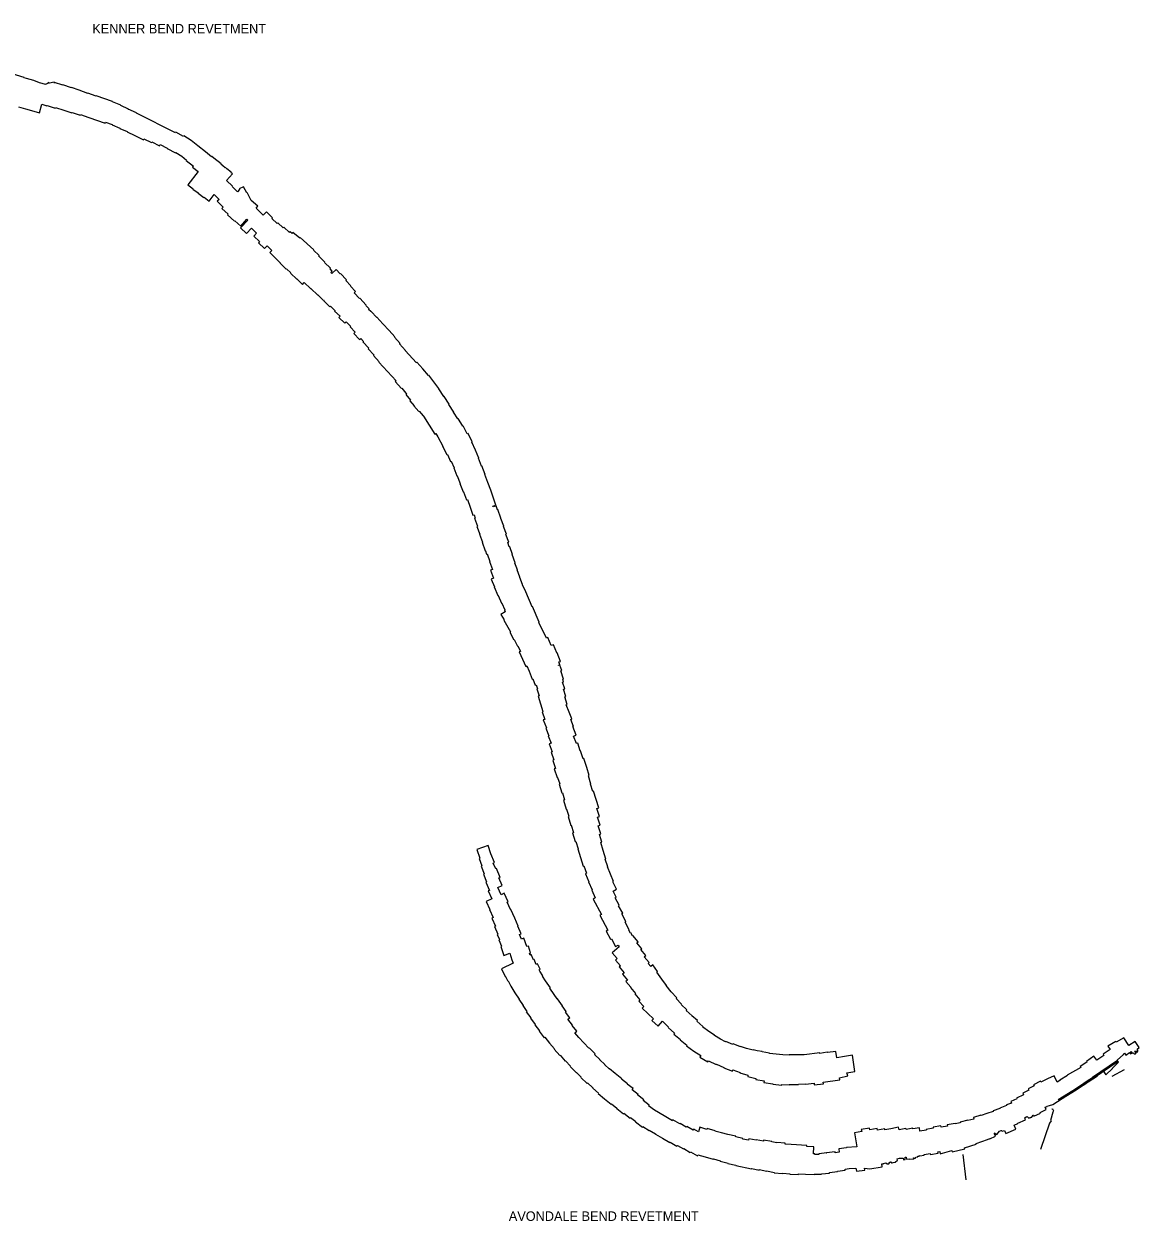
# Model space of a CAD drawing. Extents: x 2650582 to 3923188, y 277893 to 989177.
# Drawn here: x 3624994 to 3643767, y 517433 to 537580 of the extents above; entities that cross this region are included whole.
import ezdxf

# ---------------------------------------------------------------- set-up
doc = ezdxf.new("R2010")
doc.units = 0
doc.layers.add('Level 3', color=7, linetype='Continuous')

msp = doc.modelspace()

# ---------------------------------------------------------------- linework, layer by layer
at = {"layer": 'Level 3'}
for p, q in [((3643403, 520136), (3642982, 519851)), ((3643409, 520127), (3642988, 519842)), ((3643414, 520119), (3642994, 519834)), ((3643517, 519977), (3643307, 519865)), ((3640799, 518556), (3640852, 518129))]:
    msp.add_line(p, q, dxfattribs=at)
for points in [[(3625365, 536560), (3625256, 536591), (3625256, 536591), (3625158, 536626), (3625158, 536628), (3625039, 536663), (3625038, 536659), (3624998, 536673), (3624999, 536678), (3624794, 536742), (3624791, 536736), (3624564, 536810), (3624567, 536823), (3624445, 536849), (3624445, 536853), (3624408, 536861), (3624322, 536889), (3624323, 536894), (3624282, 536903)], [(3628478, 535078), (3628483, 535086), (3628409, 535141), (3628385, 535164), (3628382, 535161), (3628343, 535191), (3628310, 535218), (3628315, 535226), (3628189, 535319), (3628155, 535348), (3628154, 535346), (3628048, 535426), (3628052, 535430), (3627924, 535531), (3627809, 535621), (3627809, 535620), (3627685, 535699), (3627678, 535688), (3627550, 535756), (3627544, 535746), (3627289, 535876), (3627290, 535878), (3627160, 535944), (3627161, 535946), (3627014, 536016), (3627013, 536015), (3626888, 536077), (3626891, 536083), (3626751, 536143), (3626753, 536148), (3626624, 536205), (3626627, 536215), (3626484, 536270), (3626486, 536274), (3626211, 536369), (3626210, 536367), (3626070, 536415), (3626070, 536412), (3625923, 536464), (3625923, 536463), (3625796, 536508), (3625795, 536505), (3625650, 536556), (3625647, 536548), (3625511, 536596), (3625506, 536582), (3625501, 536602), (3625427, 536584), (3625401, 536592), (3625396, 536576), (3625364, 536568), (3625365, 536560)], [(3624902, 536186), (3625021, 536152), (3625022, 536153), (3625122, 536124), (3625121, 536123), (3625256, 536084), (3625298, 536229)], [(3625298, 536229), (3625380, 536199), (3625384, 536210), (3625521, 536161), (3625526, 536174), (3625663, 536127), (3625664, 536130), (3625802, 536082), (3625805, 536091), (3625942, 536042), (3625946, 536054), (3626084, 536006), (3626085, 536008), (3626360, 535912), (3626366, 535929), (3626482, 535885), (3626481, 535883), (3626610, 535826), (3626608, 535823), (3626732, 535769), (3626731, 535767), (3626861, 535703), (3626860, 535700), (3627005, 535630), (3627013, 535647), (3627139, 535583), (3627147, 535598), (3627279, 535531), (3627288, 535549), (3627407, 535487), (3627405, 535482), (3627545, 535408), (3627549, 535416), (3627650, 535352), (3627731, 535290), (3627726, 535284), (3627848, 535187), (3627834, 535170), (3627928, 535099)], [(3627928, 535099), (3627755, 534870), (3627842, 534804), (3627840, 534801), (3627927, 534735), (3627926, 534734), (3628025, 534659), (3628029, 534664), (3628115, 534599), (3628197, 534707)], [(3628902, 534481), (3628930, 534514), (3628818, 534610), (3628753, 534742), (3628745, 534738), (3628692, 534841), (3628619, 534803), (3628623, 534795), (3628589, 534757), (3628500, 534842), (3628505, 534848), (3628402, 534947), (3628503, 535055), (3628478, 535078)], [(3628197, 534707), (3628279, 534628), (3628247, 534595), (3628348, 534499), (3628325, 534473), (3628430, 534376), (3628423, 534369), (3628541, 534260), (3628544, 534264), (3628645, 534178), (3628744, 534294)], [(3628744, 534294), (3628762, 534277), (3628638, 534148), (3628739, 534051), (3628826, 534142), (3628912, 534058), (3628866, 534010), (3628961, 533917), (3628941, 533895), (3629042, 533798), (3629087, 533845), (3629168, 533766), (3629136, 533731), (3629226, 533644), (3629223, 533642), (3629312, 533556), (3629309, 533553), (3629410, 533455), (3629414, 533460)], [(3629509, 534055), (3629478, 534085), (3629463, 534069), (3629370, 534159), (3629356, 534146), (3629266, 534232), (3629256, 534221), (3629167, 534308), (3629178, 534319), (3629077, 534416), (3629023, 534360), (3628941, 534440), (3628943, 534442), (3628902, 534481)], [(3632471, 530686), (3632457, 530680), (3632387, 530814), (3632382, 530811), (3632306, 530940), (3632298, 530935), (3632226, 531046), (3632230, 531049), (3632149, 531176), (3632153, 531179), (3632067, 531310), (3632063, 531308), (3631976, 531441), (3631979, 531443), (3631808, 531667), (3631804, 531664), (3631708, 531776), (3631707, 531775), (3631610, 531886), (3631602, 531878), (3631413, 532082), (3631418, 532087), (3631319, 532196), (3631328, 532204), (3631233, 532311), (3631236, 532314), (3631140, 532421), (3631142, 532423), (3631036, 532535), (3630937, 532643), (3630934, 532639), (3630837, 532741), (3630834, 532739), (3630797, 532777), (3630807, 532788), (3630750, 532843), (3630756, 532848), (3630651, 532965), (3630641, 532957), (3630552, 533054), (3630578, 533079), (3630493, 533168), (3630500, 533175), (3630413, 533264), (3630424, 533275), (3630323, 533380), (3630319, 533377), (3630251, 533448), (3630180, 533381), (3630162, 533397), (3630185, 533421), (3630147, 533459), (3630156, 533468), (3630056, 533567), (3630061, 533572), (3629959, 533674), (3629966, 533681), (3629869, 533775), (3629874, 533781), (3629647, 533986), (3629637, 533977), (3629522, 534071), (3629509, 534055)], [(3629414, 533460), (3629489, 533391), (3629484, 533385), (3629588, 533287), (3629591, 533290), (3629682, 533196), (3629714, 533226), (3629817, 533126), (3629822, 533130), (3629941, 533018), (3629943, 533020), (3630039, 532927), (3630045, 532932), (3630051, 532926)], [(3630051, 532926), (3630043, 532918), (3630144, 532821), (3630153, 532831), (3630232, 532754), (3630225, 532747), (3630315, 532660), (3630297, 532641), (3630398, 532544), (3630418, 532565), (3630494, 532491), (3630484, 532481), (3630570, 532391), (3630549, 532370), (3630646, 532269), (3630664, 532287)], [(3630664, 532287), (3630709, 532237), (3630702, 532230), (3630800, 532125), (3630789, 532115), (3630884, 532009), (3630877, 532002), (3630975, 531896), (3630967, 531888), (3631259, 531576), (3631246, 531564), (3631353, 531446), (3631356, 531449), (3631425, 531366), (3631423, 531364), (3631433, 531351), (3631422, 531342), (3631504, 531248), (3631491, 531236), (3631563, 531154), (3631559, 531151), (3631640, 531057), (3631648, 531064), (3631714, 530982), (3631716, 530984), (3631719, 530981), (3631910, 530677)], [(3631910, 530677), (3631929, 530689), (3631962, 530633), (3631960, 530631), (3632045, 530476), (3632043, 530474), (3632114, 530332), (3632122, 530335), (3632177, 530215), (3632189, 530220), (3632237, 530112), (3632231, 530109), (3632284, 529976), (3632287, 529977), (3632338, 529848), (3632333, 529846), (3632388, 529704), (3632392, 529706), (3632446, 529572), (3632461, 529577), (3632509, 529447), (3632506, 529446), (3632552, 529311), (3632571, 529317), (3632590, 529264)], [(3632970, 529407), (3632966, 529405), (3632943, 529471), (3632894, 529454), (3632890, 529465), (3632939, 529483), (3632852, 529731), (3632855, 529732), (3632802, 529864), (3632805, 529865), (3632752, 529996), (3632757, 529998), (3632702, 530142), (3632697, 530140), (3632646, 530271), (3632650, 530273), (3632596, 530405), (3632597, 530405), (3632535, 530543), (3632540, 530545), (3632471, 530686)], [(3632590, 529264), (3632577, 529260), (3632627, 529128), (3632618, 529125), (3632667, 528993), (3632662, 528991), (3632712, 528859), (3632706, 528857), (3632761, 528711)], [(3633141, 528852), (3633158, 528858), (3633108, 528990), (3633116, 528993), (3633065, 529125), (3633071, 529128), (3633020, 529259), (3633024, 529261), (3632970, 529407)], [(3634064, 526552), (3634075, 526555), (3634031, 526694), (3634048, 526700), (3634018, 526791), (3633994, 526783), (3633992, 526789), (3634016, 526797), (3634001, 526842), (3634025, 526851), (3633972, 526999), (3633963, 526996), (3633910, 527133), (3633869, 527118), (3633811, 527253), (3633789, 527243), (3633665, 527508), (3633669, 527510), (3633555, 527774), (3633550, 527772), (3633442, 528020), (3633444, 528021), (3633388, 528143), (3633390, 528144), (3633340, 528265), (3633345, 528267), (3633296, 528393), (3633301, 528395), (3633258, 528508), (3633263, 528510), (3633211, 528650), (3633218, 528652), (3633172, 528781), (3633165, 528779), (3633141, 528852)], [(3632761, 528711), (3632763, 528711), (3632782, 528658), (3632795, 528662), (3632839, 528536), (3632831, 528533), (3632881, 528397), (3632849, 528385), (3632901, 528253), (3632862, 528237), (3632916, 528108), (3632911, 528106), (3632973, 527960), (3632978, 527962), (3633036, 527833), (3633039, 527834), (3633089, 527720), (3633084, 527718), (3633097, 527689)], [(3633097, 527689), (3633021, 527643), (3633077, 527550), (3633072, 527547), (3633143, 527427), (3633183, 527347), (3633176, 527343), (3633239, 527217), (3633247, 527221), (3633304, 527110), (3633309, 527112), (3633356, 527021), (3633333, 527011), (3633442, 526769), (3633461, 526778), (3633501, 526687), (3633497, 526685), (3633548, 526555), (3633564, 526561), (3633600, 526451), (3633619, 526457)], [(3633619, 526457), (3633638, 526392), (3633630, 526389), (3633668, 526271), (3633649, 526265), (3633727, 526010), (3633718, 526006), (3633764, 525877), (3633738, 525866), (3633789, 525736), (3633778, 525731), (3633829, 525601), (3633820, 525597), (3633869, 525474), (3633837, 525462), (3633884, 525329), (3633871, 525324), (3633917, 525193), (3633898, 525186), (3633944, 525052), (3633919, 525044), (3633970, 524897), (3633976, 524899), (3634016, 524791), (3634004, 524787), (3634048, 524638), (3634058, 524641), (3634096, 524520), (3634078, 524514), (3634124, 524365), (3634130, 524366), (3634169, 524247), (3634158, 524244), (3634203, 524093), (3634207, 524095), (3634245, 523974), (3634229, 523969), (3634273, 523820), (3634285, 523823), (3634325, 523698), (3634319, 523695), (3634409, 523408), (3634420, 523412), (3634464, 523286), (3634448, 523278), (3634505, 523143), (3634500, 523140), (3634561, 523007), (3634552, 523003), (3634613, 522871), (3634575, 522848), (3634716, 522592), (3634692, 522579), (3634824, 522328), (3634795, 522313), (3634869, 522175), (3634886, 522183), (3634954, 522053), (3635000, 522076)], [(3635243, 522239), (3635239, 522236), (3635212, 522286), (3635203, 522281), (3635178, 522330), (3635184, 522333), (3635117, 522465), (3635129, 522473), (3635059, 522604), (3635075, 522615), (3635005, 522740), (3635017, 522749), (3634946, 522874), (3634962, 522883), (3634912, 522988), (3634970, 523019), (3634908, 523144), (3634917, 523148), (3634866, 523273), (3634817, 523392), (3634825, 523395), (3634779, 523521), (3634788, 523524), (3634745, 523668), (3634704, 523802), (3634721, 523808), (3634681, 523941), (3634704, 523949), (3634662, 524084), (3634696, 524096), (3634652, 524231), (3634681, 524240), (3634641, 524377), (3634672, 524387), (3634582, 524667), (3634573, 524665), (3634534, 524784), (3634540, 524786), (3634497, 524929), (3634511, 524934), (3634470, 525065), (3634418, 525217), (3634408, 525214), (3634363, 525348), (3634357, 525346), (3634317, 525476), (3634295, 525468), (3634245, 525592), (3634291, 525611), (3634235, 525755), (3634244, 525759), (3634199, 525876), (3634216, 525883), (3634174, 525996), (3634125, 526119), (3634142, 526125), (3634100, 526257), (3634116, 526262), (3634077, 526382), (3634098, 526389), (3634060, 526503), (3634076, 526509), (3634064, 526552)], [(3633411, 522193), (3633371, 522179), (3633339, 522255), (3633365, 522267), (3633307, 522395), (3633317, 522399), (3633257, 522532), (3633258, 522533), (3633192, 522678), (3633186, 522675), (3633130, 522798), (3633147, 522806), (3633080, 522951), (3633026, 522926), (3632972, 523049), (3633045, 523081), (3632988, 523209), (3633009, 523217), (3632947, 523364), (3632937, 523359), (3632896, 523459), (3632914, 523466), (3632857, 523614), (3632856, 523614), (3632808, 523751), (3632618, 523684), (3632668, 523542), (3632655, 523537), (3632703, 523412), (3632689, 523406), (3632742, 523277), (3632728, 523272), (3632784, 523140), (3632771, 523134), (3632830, 522998), (3632811, 522989), (3632870, 522855), (3632776, 522812), (3632837, 522679), (3632831, 522676), (3632893, 522541), (3632870, 522531), (3632930, 522398), (3632914, 522391), (3632972, 522264), (3632959, 522258), (3632999, 522171), (3632987, 522166), (3633032, 522058), (3633021, 522055)], [(3635546, 521718), (3635504, 521768), (3635521, 521782), (3635438, 521881), (3635464, 521902), (3635380, 522002), (3635394, 522013), (3635310, 522113), (3635333, 522132), (3635243, 522239)], [(3633021, 522055), (3633074, 521904), (3633174, 521940), (3633208, 521832), (3633206, 521831), (3633231, 521773)], [(3633534, 521917), (3633519, 521910), (3633506, 521938), (3633523, 521949), (3633488, 522061), (3633462, 522053), (3633411, 522193)], [(3635000, 522076), (3635015, 522048), (3634897, 521950), (3634981, 521850), (3634952, 521826), (3635036, 521726), (3635016, 521710), (3635099, 521611), (3635069, 521586), (3635153, 521487), (3635129, 521466), (3635212, 521367), (3635208, 521363), (3635291, 521263), (3635281, 521255), (3635365, 521155), (3635344, 521135), (3635431, 521046), (3635404, 521016), (3635499, 520928), (3635594, 520839), (3635567, 520809), (3635669, 520714), (3635746, 520797)], [(3635678, 519259), (3635677, 519258), (3635607, 519298), (3635510, 519371), (3635520, 519385), (3635420, 519460), (3635432, 519476), (3635326, 519556), (3635333, 519565), (3635231, 519642), (3635248, 519664), (3635151, 519737), (3635156, 519742), (3635056, 519823), (3635057, 519825), (3634948, 519918), (3634945, 519915), (3634852, 519996), (3634849, 519993), (3634772, 520064), (3634775, 520066), (3634688, 520149), (3634691, 520153), (3634601, 520238), (3634608, 520245), (3634507, 520346), (3634503, 520343), (3634421, 520431), (3634420, 520431), (3634336, 520525), (3634334, 520523), (3634267, 520602), (3634300, 520631), (3634223, 520723), (3634230, 520729), (3634151, 520830), (3634182, 520854), (3634109, 520947), (3634125, 520959), (3634053, 521054), (3634058, 521058), (3633975, 521174), (3633972, 521171), (3633918, 521247), (3633918, 521248), (3633847, 521351), (3633858, 521358), (3633777, 521476), (3633776, 521475), (3633722, 521555), (3633729, 521559), (3633679, 521638), (3633667, 521660), (3633686, 521670), (3633639, 521761), (3633620, 521751), (3633583, 521833), (3633575, 521830), (3633534, 521917)], [(3633231, 521773), (3633034, 521680), (3633097, 521548), (3633103, 521551), (3633139, 521472), (3633145, 521475), (3633191, 521388), (3633189, 521387), (3633261, 521273), (3633260, 521273), (3633330, 521170), (3633326, 521167), (3633397, 521063), (3633392, 521059), (3633459, 520961), (3633451, 520955), (3633525, 520852), (3633522, 520849), (3633599, 520741), (3633594, 520737), (3633672, 520635), (3633667, 520631), (3633754, 520519), (3633764, 520527), (3633843, 520426), (3633843, 520426), (3633924, 520330), (3633923, 520329), (3634014, 520221), (3634019, 520225), (3634106, 520127), (3634111, 520131), (3634197, 520039), (3634191, 520033), (3634292, 519932), (3634294, 519934), (3634375, 519856), (3634370, 519851), (3634475, 519751), (3634481, 519759), (3634574, 519674), (3634572, 519672), (3634669, 519588), (3634662, 519580), (3634768, 519491), (3634766, 519489), (3634878, 519398), (3634883, 519404), (3634978, 519333), (3634973, 519327), (3635088, 519240), (3635093, 519247), (3635199, 519167), (3635204, 519175), (3635295, 519107), (3635291, 519102), (3635406, 519016), (3635411, 519022), (3635519, 518959), (3635520, 518961)], [(3638983, 519952), (3638942, 520224), (3638809, 520202), (3638809, 520201), (3638677, 520182), (3638662, 520289), (3638521, 520268), (3638519, 520276), (3638392, 520256), (3638392, 520262), (3638128, 520230), (3637876, 520230), (3637876, 520226), (3637768, 520229), (3637715, 520234), (3637657, 520241), (3637543, 520253), (3637544, 520261), (3637423, 520280), (3637424, 520285), (3637340, 520301), (3637272, 520314), (3637272, 520312), (3637157, 520337), (3637060, 520371), (3637057, 520365), (3636935, 520414), (3636931, 520405), (3636809, 520457), (3636806, 520452), (3636719, 520495), (3636720, 520496), (3636617, 520557), (3636620, 520561), (3636522, 520624), (3636523, 520626), (3636419, 520704), (3636424, 520710), (3636323, 520795), (3636333, 520807), (3636239, 520885), (3636241, 520888), (3636145, 520978), (3636154, 520987), (3636061, 521078), (3636065, 521082), (3635973, 521180), (3635983, 521189), (3635891, 521293), (3635807, 521397), (3635811, 521400), (3635731, 521502), (3635734, 521505), (3635650, 521623), (3635662, 521631), (3635582, 521743), (3635546, 521718)], [(3635746, 520797), (3635848, 520697), (3635842, 520692), (3635946, 520595), (3635933, 520578), (3636047, 520488), (3636043, 520483), (3636155, 520393), (3636149, 520384), (3636269, 520294), (3636269, 520294), (3636387, 520217), (3636373, 520193), (3636509, 520114), (3636519, 520131), (3636649, 520068), (3636652, 520074), (3636778, 520018), (3636776, 520014), (3636921, 519955), (3636929, 519978), (3637050, 519935), (3637048, 519927), (3637183, 519891), (3637178, 519864), (3637317, 519834), (3637315, 519816), (3637454, 519793), (3637451, 519765), (3637603, 519745), (3637603, 519735), (3637754, 519723), (3637755, 519732), (3637877, 519728), (3637877, 519730), (3638031, 519730), (3638031, 519737), (3638150, 519743), (3638152, 519735), (3638296, 519752), (3638299, 519728), (3638454, 519745), (3638451, 519772), (3638732, 519809), (3638726, 519844), (3638862, 519878), (3638848, 519930), (3638983, 519952)], [(3643767, 520355), (3643699, 520457), (3643593, 520389), (3643511, 520516), (3643384, 520443), (3643376, 520456), (3643244, 520378)], [(3643244, 520378), (3643278, 520318), (3643160, 520244), (3643176, 520217), (3643057, 520140), (3643007, 520206), (3642883, 520117), (3642890, 520105), (3642778, 520032)], [(3643396, 520142), (3643503, 520234), (3643501, 520239), (3643521, 520258), (3643544, 520224), (3643604, 520270), (3643622, 520247), (3643638, 520260), (3643621, 520283), (3643630, 520289), (3643653, 520258), (3643670, 520266), (3643682, 520250), (3643701, 520249), (3643716, 520257), (3643696, 520290), (3643705, 520298), (3643727, 520272), (3643741, 520283), (3643742, 520290), (3643750, 520296), (3643734, 520324), (3643767, 520355)], [(3642778, 520032), (3642785, 520019), (3642557, 519889), (3642560, 519885), (3642432, 519805), (3642436, 519798), (3642389, 519770), (3642336, 519879), (3642226, 519825), (3642226, 519827), (3642116, 519773), (3642110, 519786), (3641991, 519728), (3642001, 519708), (3641899, 519658), (3641911, 519634), (3641809, 519584), (3641821, 519559)], [(3643065, 519877), (3643060, 519886), (3643165, 519960), (3643208, 519895), (3643321, 520000), (3643318, 520005), (3643419, 520105), (3643396, 520142)], [(3642219, 519366), (3642260, 519381), (3642261, 519378), (3642313, 519396), (3643065, 519877)], [(3641821, 519559), (3641704, 519502), (3641709, 519493), (3641606, 519443), (3641618, 519420), (3641533, 519389), (3641537, 519377), (3641422, 519335), (3641424, 519330), (3641310, 519288), (3641313, 519280), (3641207, 519241), (3641206, 519246), (3641107, 519210), (3641106, 519213), (3640980, 519174), (3640987, 519149), (3640885, 519124), (3640884, 519131), (3640756, 519099), (3640758, 519088), (3640670, 519072), (3640669, 519077), (3640539, 519054), (3640543, 519032), (3640433, 519013), (3640429, 519036)], [(3636374, 519012), (3636348, 518933), (3636270, 518978), (3636262, 518964), (3636152, 519027), (3636144, 519014), (3636041, 519074), (3636037, 519067), (3635920, 519135), (3635913, 519122), (3635802, 519186), (3635803, 519187), (3635678, 519259)], [(3641329, 518921), (3641370, 518891), (3641415, 518949), (3641443, 518957), (3641455, 518955), (3641461, 518944), (3641500, 518960), (3641524, 518908), (3641695, 518982), (3641665, 519049), (3641726, 519073), (3641724, 519082), (3641856, 519135), (3641845, 519169), (3641868, 519189), (3641884, 519191), (3641912, 519164), (3641933, 519177), (3641946, 519175), (3641952, 519184), (3641960, 519184), (3641968, 519197), (3641979, 519202), (3641976, 519213), (3641988, 519218), (3641998, 519197), (3642109, 519251), (3642103, 519263), (3642205, 519313), (3642188, 519348), (3642220, 519362), (3642219, 519366)], [(3642299, 519323), (3642309, 519321), (3642328, 519286), (3642318, 519268), (3642276, 519127), (3642286, 519118), (3642259, 519083), (3642109, 518638)], [(3638289, 518566), (3638293, 518683), (3638175, 518689), (3638176, 518703), (3637911, 518722), (3637911, 518721), (3637807, 518728), (3637809, 518743), (3637670, 518757), (3637669, 518752), (3637583, 518767), (3637583, 518770), (3637446, 518795), (3637443, 518777), (3637319, 518798), (3637319, 518797), (3637196, 518819), (3637192, 518797), (3637097, 518813), (3637099, 518822), (3636977, 518851), (3636979, 518860), (3636843, 518892), (3636843, 518891), (3636735, 518916), (3636736, 518919), (3636626, 518945), (3636629, 518952), (3636495, 518991), (3636490, 518974), (3636374, 519012)], [(3639589, 518984), (3639489, 518966), (3639486, 518985), (3639362, 518963), (3639358, 518989), (3639235, 518967), (3639229, 518998), (3639091, 518973), (3639098, 518938), (3638975, 518916), (3639016, 518684), (3638842, 518671), (3638842, 518665), (3638714, 518651), (3638720, 518592), (3638653, 518584), (3638651, 518599), (3638507, 518583), (3638508, 518579), (3638375, 518564), (3638376, 518553), (3638307, 518555), (3638307, 518565), (3638289, 518566)], [(3640429, 519036), (3640299, 519013), (3640302, 518994), (3640182, 518973), (3640184, 518965), (3640078, 518946), (3640068, 519004), (3639961, 518986), (3639959, 518995), (3639844, 518974), (3639841, 518989), (3639726, 518968), (3639719, 519011), (3639589, 518988), (3639589, 518984)], [(3635520, 518961), (3635627, 518899), (3635627, 518898), (3635744, 518830), (3635742, 518826), (3635867, 518754), (3635871, 518761), (3635988, 518694), (3635996, 518707), (3636099, 518647), (3636101, 518652), (3636211, 518588), (3636218, 518600), (3636333, 518533), (3636341, 518547), (3636461, 518514), (3636460, 518514), (3636599, 518475), (3636601, 518481), (3636717, 518449), (3636715, 518444), (3636847, 518407), (3636846, 518403), (3636977, 518375), (3636976, 518370), (3637245, 518313), (3637246, 518317), (3637372, 518290), (3637374, 518300), (3637502, 518273), (3637503, 518277), (3637622, 518251), (3637622, 518246), (3637766, 518234), (3637766, 518239), (3637891, 518229), (3637890, 518224), (3638035, 518217), (3638036, 518227), (3638152, 518222), (3638152, 518220), (3638298, 518216), (3638298, 518225), (3638422, 518222), (3638422, 518226), (3638558, 518241), (3638557, 518253), (3638689, 518268), (3638688, 518273), (3638820, 518288), (3638818, 518309), (3638884, 518316), (3638999, 518326), (3639008, 518272), (3639148, 518291), (3639143, 518325), (3639234, 518315), (3639440, 518347), (3639438, 518394)], [(3640411, 518602), (3640421, 518567), (3640614, 518620), (3640619, 518601), (3640833, 518651), (3640830, 518665), (3641027, 518729), (3641023, 518741), (3641217, 518807), (3641253, 518824), (3641257, 518817), (3641353, 518861), (3641331, 518903), (3641331, 518915), (3641329, 518921)], [(3639438, 518394), (3639462, 518398), (3639461, 518403), (3639504, 518411), (3639525, 518398), (3639552, 518398), (3639567, 518413), (3639566, 518422), (3639584, 518425), (3639583, 518431), (3639586, 518432), (3639587, 518428), (3639596, 518429), (3639599, 518411), (3639613, 518413), (3639628, 518420), (3639659, 518424), (3639700, 518459), (3639697, 518483), (3639735, 518490), (3639773, 518492), (3639795, 518490), (3639800, 518465), (3639831, 518470), (3639828, 518486), (3639831, 518486), (3639828, 518509), (3639844, 518510), (3639845, 518509), (3639851, 518474), (3639900, 518482), (3639905, 518477), (3639974, 518481), (3639972, 518495), (3639982, 518498), (3639986, 518486), (3640004, 518497), (3640004, 518504), (3640010, 518505), (3640010, 518510), (3640043, 518516), (3640042, 518524), (3640063, 518528), (3640063, 518530), (3640074, 518534), (3640075, 518529), (3640149, 518543), (3640148, 518552), (3640253, 518571), (3640256, 518555), (3640386, 518577), (3640382, 518597), (3640411, 518602)]]:
    msp.add_lwpolyline(points, dxfattribs=at)
for centre in [(3636582, 529163), (3636589, 529155), (3636595, 529146)]:
    msp.add_ellipse(centre, major_axis=(9602, 5982), ratio=0.998746, start_param=4.696537, end_param=4.757308, dxfattribs=at)

# ---------------------------------------------------------------- texts
for s, p in [('KENNER BEND REVETMENT', (3626145, 537420)), ('AVONDALE BEND REVETMENT', (3633157, 517436))]:
    msp.add_text(s, height=160, dxfattribs=at).set_placement(p)

doc.saveas('drawing.dxf')
